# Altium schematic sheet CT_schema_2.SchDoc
size 403 x 258 mm
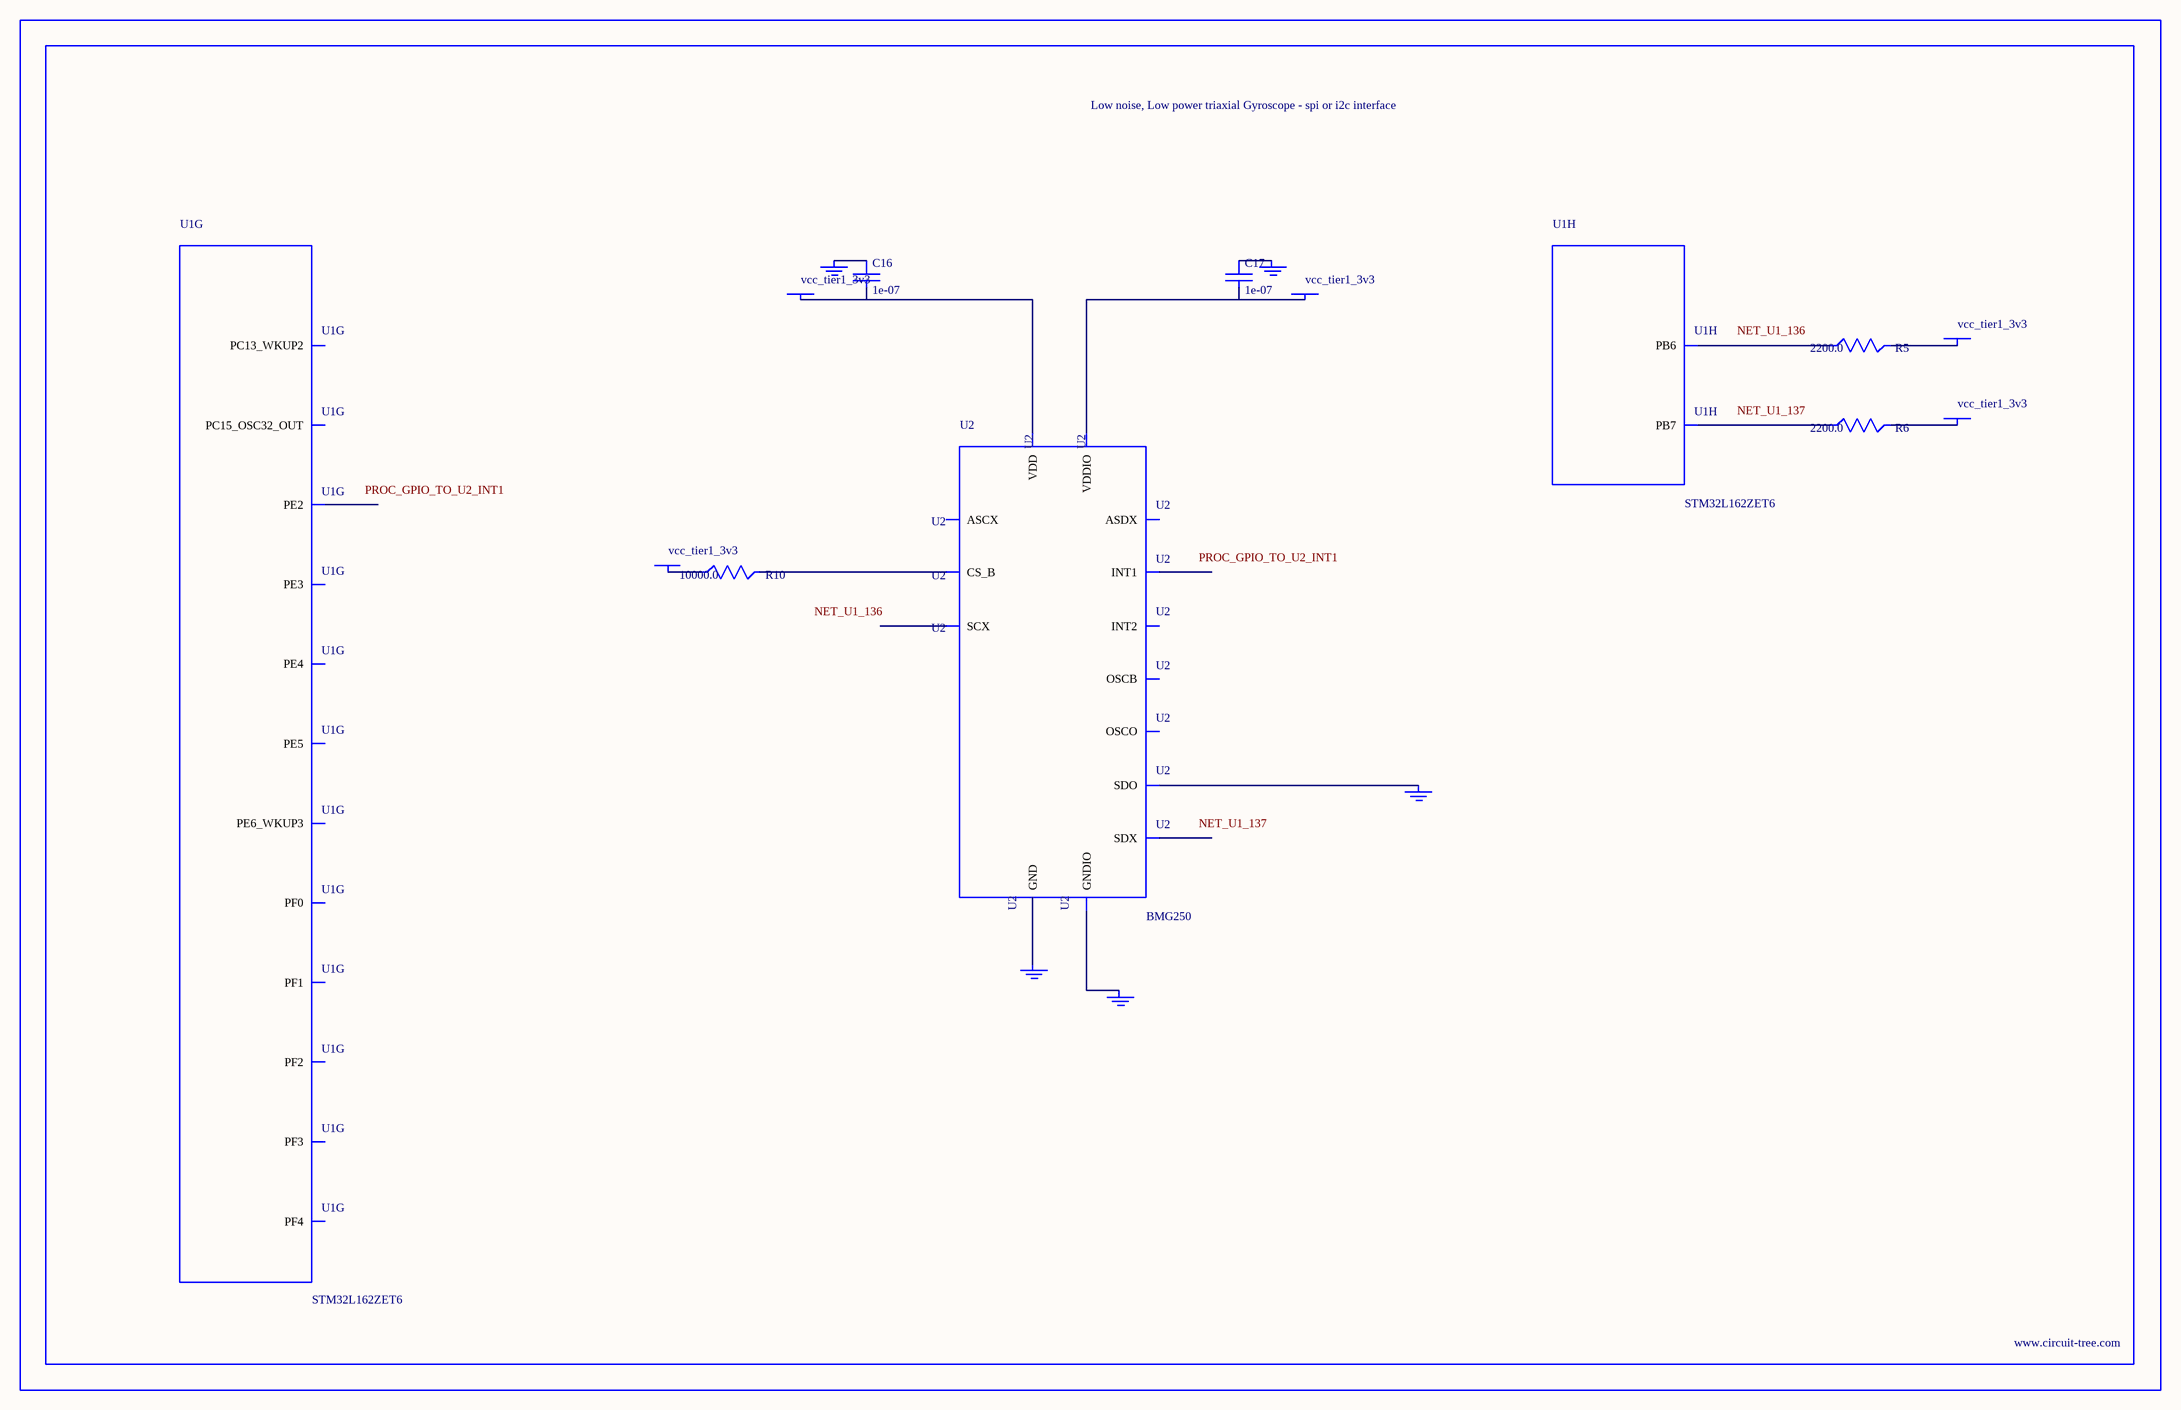
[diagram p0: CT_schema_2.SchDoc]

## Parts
BORDER1  (no value)
C16  1e-07  [C0402]
C17  1e-07  [C0402]
GND_INSTANCE_1_0  (no value)
GND_INSTANCE_1_1  (no value)
GND_INSTANCE_1_2  (no value)
GND_INSTANCE_1_3  (no value)
GND_INSTANCE_1_4  (no value)
POWER_INSTANCE_1_0  vcc_tier1_3v3
POWER_INSTANCE_1_1  vcc_tier1_3v3
POWER_INSTANCE_1_2  vcc_tier1_3v3
POWER_INSTANCE_1_3  vcc_tier1_3v3
POWER_INSTANCE_1_4  vcc_tier1_3v3
R5  2200.0  [R0603]
R6  2200.0  [R0603]
R10  10000.0  [R0603]
U1  STM32L162ZET6  [LQFP144]  (parts G,H of 13)
U2  BMG250  [LGA-14]

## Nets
NetC16_1: C16.1 GND_INSTANCE_1_3.0(GND)
NetC16_2: C16.2 POWER_INSTANCE_1_1.0(PWR) U2.8(VDD)
NetC17_1: C17.1 GND_INSTANCE_1_1.0(GND)
NetC17_2: C17.2 POWER_INSTANCE_1_0.0(PWR) U2.5(VDDIO)
NetGND_INSTANCE_1_0_0: GND_INSTANCE_1_0.0(GND) U2.1(SDO)
NetGND_INSTANCE_1_2_0: GND_INSTANCE_1_2.0(GND) U2.6(GNDIO)
NetGND_INSTANCE_1_4_0: GND_INSTANCE_1_4.0(GND) U2.7(GND)
NetPOWER_INSTANCE_1_2_0: POWER_INSTANCE_1_2.0(PWR) R10.1
NetPOWER_INSTANCE_1_3_0: POWER_INSTANCE_1_3.0(PWR) R5.2
NetPOWER_INSTANCE_1_4_0: POWER_INSTANCE_1_4.0(PWR) R6.2
NetR5_1: R5.1 U1.136(PB6)
NetR6_1: R6.1 U1.137(PB7)
NetR10_2: R10.2 U2.12(CS_B)

Not connected (* = marked no-connect by the designer): U1 1(PE2) 2(PE3) 3(PE4) 4(PE5) 5(PE6_WKUP3) 7(PC13_WKUP2) 9(PC15_OSC32_OUT) 10(PF0) 11(PF1) 12(PF2) 13(PF3) 14(PF4); U2 2(ASDX) 3(ASCX) 4(INT1) 9(INT2) 10(OSCB) 11(OSCO) 13(SCX) 14(SDX)

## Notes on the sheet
- Labels drawn without touching a wire or pin: NET_U1_136, NET_U1_137, PROC_GPIO_TO_U2_INT1

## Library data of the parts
BORDER1 = BORDER_PAGE1
C16 C17 = C0402C104K3RACTU
GND_INSTANCE_1_0-GND_INSTANCE_1_4 = GND
POWER_INSTANCE_1_0-POWER_INSTANCE_1_4 = PWR
R5 R6 = RC0603JR-072K2L
R10 = RC0603JR-0710KL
